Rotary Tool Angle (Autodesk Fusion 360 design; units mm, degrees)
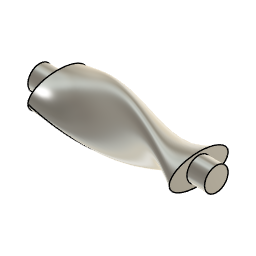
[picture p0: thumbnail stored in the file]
work_plane "WorkPlane1" AlongDistance 76.2
work_plane "WorkPlane2" AlongDistance -76.2
sketch "Sketch1" plane through (0, 0, 0) normal (1, 0, 0) x axis (0, 1, 0)
  curve K1 (0, 31.75) -> (0, -31.75)
  curve K2 (-15.875, 0) -> (15.875, 0)
  circle C1 centre (0, 0) radius 12.7
  closed curve K3 centre (0, 0)
  point P1 (0, 0)
  point P2 (0, 0)
  point P4 (0, -31.75)
  point P5 (0, 31.75)
  point P6 (15.875, 0)
  point P7 (-15.875, 0)
  point P3 (0, 0)
  coincident P1 P2
  coincident K3 P4
  coincident K3 P5
  coincident K3 P6
  coincident K3 P7
  coincident P1 P3
  vertical K1
  dimension "d3" diameter C1 = 25.4
  dimension "d4" distance K3 = 31.75
  dimension "d5" distance K3 = 63.5
sketch "Sketch2" plane through (76.2, 0, 0) normal (1, 0, 0) x axis (0, 1, 0)
  curve K1 (31.75, 0) -> (-31.75, 0)
  curve K2 (0, 15.875) -> (0, -15.875)
  circle C1 centre (0, 0) radius 12.7
  closed curve K3 centre (0, 0)
  point P1 (0, 0)
  point P2 (0, 0)
  point P4 (-31.75, 0)
  point P5 (31.75, 0)
  point P6 (0, -15.875)
  point P7 (0, 15.875)
  point P3 (0, 0)
  coincident P1 P2
  coincident K3 P4
  coincident K3 P5
  coincident K3 P6
  coincident K3 P7
  coincident P1 P3
  horizontal K1
  dimension "d6" diameter C1 = 25.4
  dimension "d7" distance K3 = 31.75
  dimension "d8" distance K3 = 63.5
sketch "Sketch3" plane through (-76.2, 0, 0) normal (1, 0, 0) x axis (0, 1, 0)
  closed curve K1 centre (0, 0)
loft "Loft1" sketch "Sketch3" + "Sketch1" + "Sketch2"
sketch "Sketch4" plane through (0, 0, 0) normal (1, 0, 0) x axis (0, 1, 0)
  circle C1 centre (0, 0) radius 12.7
  point P1 (0, 0)
  point P2 (0, 0)
  coincident P1 P2
  dimension "d9" diameter C1 = 25.4
extrude "Extrude1" add sketch "Sketch4" distance 95.25
step "SurfaceOffset" offset 1.27
surface_patch "SurfacePatch1"
surface_patch "SurfacePatch2"
surface_stitch "SurfaceStitch1" StitchingTolerence 0.1016 bodies "Stock"
extrude "Extrude2" add sketch "Sketch4" distance 95.25
named bodies: "Stock"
